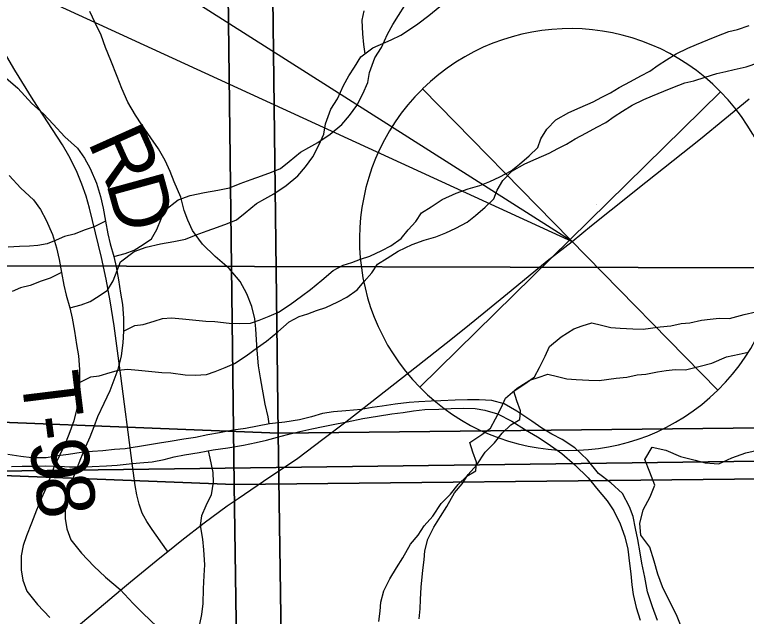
# Model space of a CAD drawing. Extents: x -21.1 to 50.3, y -4.9 to 22.1.
# Drawn here: x 4.587 to 5.308, y 16.789 to 17.38 of the extents above; entities that cross this region are included whole.
import ezdxf

# ---------------------------------------------------------------- set-up
doc = ezdxf.new("R2010")
doc.units = 0
for name, color, linetype in [('GM_X_Major_River', 7, 'Continuous'), ('GM_X_Minor_River', 7, 'Continuous'), ('GM_X_Section', 7, 'Continuous'), ('GM_X_State_Location', 7, 'Continuous'), ('GM_X_State_Route', 7, 'Continuous'), ('GM_X_Township_Road', 7, 'Continuous'), ('GM_X_Township_Road_Text', 7, 'Continuous'), ('SH_Data', 7, 'Continuous')]:
    doc.layers.add(name, color=color, linetype=linetype)

msp = doc.modelspace()

# ---------------------------------------------------------------- linework, layer by layer
at = {"layer": 'GM_X_Major_River'}
for points in [[(4.57886, 17.31807), (4.59071, 17.30792), (4.60449, 17.29285), (4.61595, 17.2827), (4.62552, 17.27253), (4.63701, 17.2601), (4.64924, 17.24881), (4.65615, 17.239), (4.66192, 17.2288), (4.6681, 17.21443), (4.672, 17.20156), (4.67475, 17.18982), (4.67675, 17.17731), (4.67912, 17.16481), (4.68148, 17.15496), (4.68499, 17.14247), (4.68735, 17.13224), (4.68973, 17.11936), (4.69173, 17.10647), (4.69372, 17.09511), (4.69458, 17.08183), (4.69468, 17.06893), (4.69402, 17.05754)], [(4.58223, 17.22201), (4.59372, 17.20958), (4.60595, 17.1983), (4.61286, 17.18849), (4.61863, 17.17829), (4.62481, 17.16392), (4.62871, 17.15105), (4.63146, 17.13931), (4.63346, 17.1268), (4.63584, 17.11429), (4.63819, 17.10445), (4.6417, 17.09195), (4.64406, 17.08173), (4.64644, 17.06884), (4.64844, 17.05596), (4.65043, 17.04459), (4.65129, 17.03131), (4.6514, 17.01841), (4.65073, 17.00702)], [(4.69402, 17.05754), (4.69222, 17.04462), (4.68891, 17.03132), (4.6852, 17.02066), (4.68111, 17.01038), (4.67514, 16.99781), (4.66917, 16.98486), (4.66546, 16.97497), (4.66136, 16.96469), (4.65726, 16.95517), (4.65243, 16.94337), (4.64721, 16.9308), (4.64238, 16.91824), (4.63904, 16.90873), (4.63722, 16.89847), (4.63733, 16.88481), (4.63893, 16.87458), (4.64281, 16.86398), (4.65316, 16.85078), (4.66541, 16.83798), (4.67688, 16.82706), (4.69139, 16.81504), (4.70402, 16.8011), (4.71397, 16.79131), (4.72735, 16.77852)], [(4.65073, 17.00702), (4.64893, 16.99411), (4.64563, 16.9808), (4.64192, 16.97015), (4.63782, 16.95987), (4.63185, 16.9473), (4.62588, 16.93435), (4.62217, 16.92445), (4.61807, 16.91417), (4.61398, 16.90465), (4.60914, 16.89285), (4.60392, 16.88029), (4.59909, 16.86773), (4.59575, 16.85821), (4.59394, 16.84795), (4.59404, 16.83429), (4.59564, 16.82406), (4.59952, 16.81347), (4.60987, 16.80027), (4.62212, 16.78746)]]:
    msp.add_lwpolyline(points, dxfattribs=at)
at = {"layer": 'GM_X_Minor_River'}
for points in [[(4.68499, 17.14247), (4.6961, 17.14529), (4.70522, 17.14876), (4.71394, 17.15413), (4.72229, 17.15987), (4.72756, 17.16902), (4.73169, 17.1793), (4.73507, 17.18767), (4.74834, 17.198), (4.76011, 17.20225), (4.77418, 17.20537), (4.78749, 17.20772), (4.79889, 17.21006), (4.80953, 17.2143), (4.82016, 17.21816), (4.83042, 17.22163), (4.8403, 17.22549), (4.84903, 17.22895), (4.85775, 17.23584), (4.86874, 17.24502), (4.87708, 17.24962), (4.88581, 17.25461), (4.89794, 17.26266), (4.90931, 17.27222), (4.91688, 17.28099), (4.92405, 17.29091), (4.93008, 17.30234), (4.93497, 17.31338), (4.93681, 17.32327), (4.94206, 17.33773), (4.94847, 17.34803), (4.95449, 17.36098), (4.95976, 17.3705), (4.96504, 17.37927), (4.97146, 17.38918)], [(4.6417, 17.09195), (4.65281, 17.09478), (4.66193, 17.09825), (4.67066, 17.10361), (4.679, 17.10936), (4.68427, 17.1185), (4.6884, 17.12878), (4.69178, 17.13716), (4.70505, 17.14749), (4.71682, 17.15173), (4.73089, 17.15485), (4.7442, 17.1572), (4.7556, 17.15954), (4.76624, 17.16378), (4.77688, 17.16764), (4.78713, 17.17112), (4.79701, 17.17497), (4.80574, 17.17844), (4.81446, 17.18532), (4.82545, 17.1945), (4.8338, 17.19911), (4.84252, 17.20409), (4.85466, 17.21214), (4.86602, 17.2217), (4.87359, 17.23048), (4.88076, 17.2404), (4.88679, 17.25182), (4.89168, 17.26287), (4.89352, 17.27275), (4.89877, 17.28722), (4.90518, 17.29751), (4.9112, 17.31046), (4.91648, 17.31999), (4.92176, 17.32875), (4.92817, 17.33867), (4.93992, 17.34747), (4.95815, 17.35555), (4.96764, 17.36016), (4.97598, 17.36552), (4.98432, 17.37127), (4.99494, 17.3793), (5.00593, 17.3881)], [(4.838, 16.97772), (4.83683, 16.98461), (4.83388, 16.99715), (4.8295, 17.02298), (4.82729, 17.03475), (4.82626, 17.05031), (4.82557, 17.06056), (4.82488, 17.07119), (4.82381, 17.08106), (4.82085, 17.09322), (4.816, 17.10577), (4.80925, 17.11795), (4.7987, 17.13054), (4.78474, 17.14239), (4.7723, 17.1546), (4.76252, 17.16794), (4.75803, 17.17822), (4.7543, 17.18772), (4.75097, 17.20064), (4.74462, 17.21586), (4.74051, 17.22613), (4.73565, 17.23678), (4.72889, 17.24821), (4.72137, 17.25926), (4.71273, 17.27183), (4.70634, 17.28135), (4.69883, 17.2943), (4.69285, 17.30762), (4.68837, 17.3194), (4.68203, 17.335), (4.6768, 17.34793), (4.6727, 17.3601), (4.66671, 17.37228), (4.66147, 17.38331)], [(4.93231, 17.34177), (4.93115, 17.35084), (4.92995, 17.36147), (4.92949, 17.37476), (4.93134, 17.38389)], [(4.69468, 17.06893), (4.70564, 17.07469), (4.71401, 17.07549), (4.72464, 17.07897), (4.73301, 17.0813), (4.74176, 17.0821), (4.7528, 17.08102), (4.77565, 17.07887), (4.78441, 17.07854), (4.7985, 17.07672), (4.8084, 17.0764), (4.81944, 17.07684), (4.82817, 17.07992), (4.83805, 17.08378), (4.84716, 17.08763), (4.85854, 17.09529), (4.86991, 17.10333), (4.87863, 17.10984), (4.88962, 17.11901), (4.90098, 17.12857), (4.91085, 17.13395), (4.91921, 17.13665), (4.92795, 17.13974), (4.93706, 17.14283), (4.94883, 17.14821), (4.95756, 17.15282), (4.9678, 17.16009), (4.9746, 17.16849), (4.98217, 17.17689), (4.98783, 17.18528), (4.99731, 17.19141), (5.00831, 17.19831), (5.02198, 17.20484), (5.03376, 17.20909), (5.04516, 17.21219), (5.05503, 17.21604), (5.0649, 17.22066), (5.07591, 17.22679), (5.08424, 17.2333), (5.09372, 17.24133), (5.10242, 17.24973), (5.10542, 17.25811), (5.11108, 17.26763), (5.12016, 17.2768), (5.13268, 17.28409), (5.14407, 17.28909), (5.1566, 17.29448), (5.16533, 17.29909), (5.17368, 17.30331), (5.18241, 17.30868), (5.19341, 17.31444), (5.20366, 17.32019), (5.21239, 17.3248), (5.22073, 17.33054), (5.22907, 17.33591), (5.23856, 17.34166), (5.24994, 17.34742), (5.2583, 17.35088), (5.26969, 17.35551), (5.27843, 17.35897), (5.2902, 17.3636), (5.29894, 17.36554), (5.31034, 17.36941)], [(4.6514, 17.01841), (4.66235, 17.02417), (4.67072, 17.02497), (4.68135, 17.02845), (4.68972, 17.03078), (4.69847, 17.03159), (4.70951, 17.03051), (4.73236, 17.02836), (4.74112, 17.02803), (4.75521, 17.0262), (4.76511, 17.02588), (4.77615, 17.02632), (4.78488, 17.02941), (4.79476, 17.03326), (4.80387, 17.03711), (4.81525, 17.04477), (4.82662, 17.05281), (4.83534, 17.05932), (4.84633, 17.0685), (4.8577, 17.07806), (4.86756, 17.08343), (4.87592, 17.08614), (4.88466, 17.08922), (4.89377, 17.09231), (4.90555, 17.0977), (4.91427, 17.1023), (4.92451, 17.10958), (4.93131, 17.11797), (4.93888, 17.12637), (4.94454, 17.13476), (4.95402, 17.14089), (4.96502, 17.14779), (4.97869, 17.15433), (4.99047, 17.15857), (5.00187, 17.16167), (5.01174, 17.16553), (5.02161, 17.17014), (5.03262, 17.17628), (5.04095, 17.18278), (5.05043, 17.19081), (5.05913, 17.19922), (5.06213, 17.20759), (5.06779, 17.21712), (5.07687, 17.22629), (5.08939, 17.23357), (5.10078, 17.23857), (5.11331, 17.24396), (5.12204, 17.24857), (5.13039, 17.25279), (5.13912, 17.25816), (5.15013, 17.26392), (5.16037, 17.26968), (5.1691, 17.27428), (5.17744, 17.28003), (5.18578, 17.28539), (5.19527, 17.29114), (5.20666, 17.2969), (5.21501, 17.30037), (5.2264, 17.30499), (5.23514, 17.30846), (5.24691, 17.31308), (5.25566, 17.31503), (5.26705, 17.31889), (5.27845, 17.32237), (5.2872, 17.32432), (5.29556, 17.32627), (5.30735, 17.32899), (5.31988, 17.33324)], [(4.67675, 17.17731), (4.66589, 17.17171), (4.65677, 17.16863), (4.64613, 17.16439), (4.63663, 17.16205), (4.62827, 17.15859), (4.61954, 17.15474), (4.61041, 17.15317), (4.60204, 17.15274), (4.59215, 17.15231), (4.58111, 17.15149)], [(4.63346, 17.1268), (4.6226, 17.1212), (4.61348, 17.11811), (4.60284, 17.11387), (4.59334, 17.11154), (4.58499, 17.10807)], [(4.98551, 16.78601), (4.98659, 16.79589), (4.98692, 16.80502), (4.98761, 16.81717), (4.98904, 16.8339), (4.99051, 16.84416), (4.99122, 16.8529), (4.9942, 16.86431), (4.99984, 16.87612), (5.00664, 16.8868), (5.01267, 16.89671), (5.02021, 16.91005), (5.02777, 16.91883), (5.03381, 16.92798), (5.04213, 16.93752), (5.05044, 16.9501), (5.05952, 16.95927), (5.06708, 16.96881), (5.07579, 16.97683), (5.08451, 16.9822), (5.08523, 16.99056), (5.08175, 17.00042), (5.07865, 17.0099), (5.0904, 17.01794), (5.09912, 17.02407), (5.10402, 17.03321), (5.10967, 17.04426), (5.1138, 17.05378), (5.12517, 17.06334), (5.13768, 17.07139), (5.14604, 17.07409), (5.15554, 17.07718), (5.16507, 17.07496), (5.17422, 17.07273), (5.18336, 17.07202), (5.19592, 17.07133), (5.20582, 17.071), (5.22256, 17.07338), (5.23321, 17.0742), (5.24347, 17.07653), (5.25184, 17.07734), (5.26325, 17.07968), (5.272, 17.08087), (5.28075, 17.08168), (5.29102, 17.08135), (5.30547, 17.08523), (5.31687, 17.08795)], [(4.94576, 16.78338), (4.94722, 16.79365), (4.94793, 16.80239), (4.95091, 16.8138), (4.95656, 16.82561), (4.96335, 16.83628), (4.96938, 16.84619), (4.97692, 16.85953), (4.98448, 16.86831), (4.99052, 16.87746), (4.99884, 16.887), (5.00715, 16.89958), (5.01623, 16.90875), (5.02379, 16.91829), (5.0325, 16.92632), (5.04123, 16.93168), (5.04194, 16.94004), (5.03846, 16.9499), (5.03536, 16.95938), (5.04711, 16.96742), (5.05583, 16.97355), (5.06073, 16.98269), (5.06638, 16.99374), (5.07051, 17.00326), (5.08188, 17.01282), (5.09439, 17.02087), (5.10275, 17.02358), (5.11225, 17.02667), (5.12178, 17.02444), (5.13093, 17.02221), (5.14007, 17.0215), (5.15263, 17.02081), (5.16253, 17.02049), (5.17927, 17.02286), (5.18992, 17.02368), (5.20018, 17.02601), (5.20855, 17.02682), (5.21996, 17.02916), (5.22871, 17.03035), (5.23746, 17.03116), (5.24774, 17.03084), (5.26218, 17.03472), (5.27358, 17.03744), (5.28801, 17.0436), (5.30056, 17.04632), (5.3093, 17.04827)], [(5.21997, 16.78457), (5.21512, 16.79788), (5.21028, 16.81271), (5.20772, 16.82714), (5.20477, 16.84082), (5.20294, 16.85108), (5.20075, 16.86399), (5.19855, 16.87501), (5.19597, 16.88678), (5.19261, 16.89629), (5.18549, 16.90923), (5.17417, 16.91993), (5.16209, 16.92911), (5.15117, 16.94245), (5.13872, 16.95429), (5.12625, 16.96233), (5.11604, 16.96771), (5.10621, 16.97346), (5.09639, 16.98035), (5.08165, 16.99031), (5.06918, 16.99759), (5.05705, 17.0007), (5.04453, 17.00154), (5.03315, 17.00161), (5.021, 17.00131), (5.00696, 17.00063), (4.99747, 17.00031), (4.98532, 16.99963), (4.97583, 16.99893), (4.96177, 16.99712), (4.94924, 16.9953), (4.93936, 16.99384), (4.92834, 16.99201), (4.91353, 16.99059), (4.90138, 16.98952), (4.89037, 16.98808), (4.87972, 16.98473), (4.86793, 16.98176), (4.8535, 16.97958), (4.83831, 16.97777), (4.81475, 16.97337), (4.80259, 16.97154), (4.78891, 16.96897), (4.77752, 16.96715), (4.76536, 16.96456), (4.75396, 16.96274), (4.74066, 16.96054), (4.73003, 16.95871), (4.71825, 16.95689), (4.69622, 16.95323), (4.68559, 16.95254), (4.67419, 16.95147), (4.66394, 16.95077), (4.65293, 16.9497), (4.6404, 16.94788), (4.63014, 16.94643), (4.61836, 16.9446), (4.60432, 16.94431), (4.5937, 16.94589), (4.58082, 16.94787)], [(4.58453, 16.93608), (4.59478, 16.9364), (4.60579, 16.93633), (4.61793, 16.93664), (4.63159, 16.93617), (4.64145, 16.93573), (4.6536, 16.93566), (4.66384, 16.93598), (4.67789, 16.93665), (4.68852, 16.93734), (4.70029, 16.93841), (4.71054, 16.93948), (4.7227, 16.94054), (4.73447, 16.94275), (4.74436, 16.94534), (4.75462, 16.94756), (4.76905, 16.94975), (4.78273, 16.95232), (4.79717, 16.95412), (4.81274, 16.95706), (4.82529, 16.95964), (4.83517, 16.96186), (4.84619, 16.96483), (4.85608, 16.96742), (4.86824, 16.97038), (4.88002, 16.97296), (4.89104, 16.97517), (4.90434, 16.97774), (4.9146, 16.97996), (4.93018, 16.98328), (4.94462, 16.98547), (4.95867, 16.98765), (4.96969, 16.9891), (4.97995, 16.99056), (4.99096, 16.99201), (5.005, 16.9923), (5.01715, 16.99298), (5.02892, 16.99329), (5.04068, 16.99284), (5.05016, 16.99126), (5.06266, 16.98777), (5.07665, 16.98047), (5.09026, 16.97204), (5.10198, 16.96514), (5.11256, 16.95825), (5.12578, 16.94868), (5.13861, 16.9376), (5.15181, 16.92462), (5.1601, 16.9147), (5.17064, 16.90212), (5.17703, 16.89221), (5.1834, 16.87965), (5.18786, 16.86672), (5.19082, 16.85456), (5.19263, 16.84051), (5.1937, 16.83026), (5.19477, 16.81964), (5.19622, 16.81014), (5.19917, 16.79722), (5.20289, 16.78468)], [(4.77787, 16.9514), (4.77964, 16.94399), (4.78259, 16.92993), (4.7829, 16.92045), (4.78092, 16.90794), (4.77554, 16.89735), (4.7713, 16.88751), (4.7701, 16.87803), (4.77229, 16.86436), (4.77336, 16.85411), (4.7744, 16.8393), (4.77357, 16.82869), (4.77311, 16.81579), (4.77263, 16.80137), (4.77142, 16.79038), (4.76946, 16.78091)], [(5.24256, 16.78022), (5.23891, 16.79015), (5.23191, 16.80355), (5.22491, 16.81771), (5.22054, 16.82993), (5.21694, 16.8429), (5.2126, 16.85665), (5.20367, 16.86856), (5.2027, 16.87997), (5.20595, 16.89322), (5.21299, 16.90602), (5.21734, 16.91773), (5.2126, 16.93034), (5.20748, 16.94295), (5.21489, 16.955), (5.22813, 16.95214), (5.24285, 16.94584), (5.25723, 16.9422), (5.26706, 16.93939), (5.28034, 16.93843), (5.29334, 16.94431), (5.3071, 16.94942), (5.32005, 16.95226)]]:
    msp.add_lwpolyline(points, dxfattribs=at)
at = {"layer": 'GM_X_Section'}
for points in [[(4.45293, 18.14262), (5.45742, 18.14589), (5.45266, 17.13084), (4.44556, 17.13365)], [(3.80452, 18.01477), (4.83425, 17.98542), (4.84683, 16.96859), (4.43354, 16.98495), (3.82173, 16.99041)], [(4.50247, 17.98887), (5.48815, 17.97251), (5.52017, 16.94387), (4.49435, 16.93023), (4.50289, 17.92975)], [(5.81893, 17.99203), (5.83147, 16.97938), (4.84683, 16.96859), (4.83425, 17.98542)], [(3.76124, 17.96425), (4.79096, 17.9349), (4.80354, 16.91807), (4.39025, 16.93443), (3.77844, 16.93989)], [(5.77564, 17.94152), (5.78818, 16.92886), (4.80354, 16.91807), (4.79096, 17.9349)], [(4.44556, 17.13365), (5.45266, 17.13084), (5.44952, 16.13321), (4.44906, 16.1053)], [(4.84683, 16.96859), (4.86162, 15.95861), (3.83586, 15.97019), (3.82173, 16.99041), (4.43354, 16.98495)], [(4.84683, 16.96859), (5.83147, 16.97938), (5.84702, 15.96751), (4.86162, 15.95861)], [(5.52017, 16.94387), (5.53343, 15.91957), (5.47621, 15.91802), (4.49511, 15.90479), (4.49436, 16.90218), (4.49435, 16.93023)], [(4.80354, 16.91807), (4.81833, 15.90809), (3.79257, 15.91968), (3.77844, 16.93989), (4.39025, 16.93443)], [(4.80354, 16.91807), (5.78818, 16.92886), (5.80373, 15.91699), (4.81833, 15.90809)]]:
    msp.add_lwpolyline(points, close=True, dxfattribs=at)
at = {"layer": 'GM_X_State_Route'}
for points in [[(4.80738, 16.90461), (4.83247, 16.92152), (4.86601, 16.94423), (4.89077, 16.96284), (4.91332, 16.97984), (4.9842, 17.03528), (5.0185, 17.062), (5.03503, 17.07557), (5.04904, 17.08711), (5.07596, 17.10909), (5.11165, 17.13813), (5.13598, 17.15729), (5.15515, 17.17289), (5.17457, 17.18842), (5.20866, 17.21548), (5.26236, 17.25817), (5.3101, 17.29753)], [(4.7382, 16.85243), (4.75199, 16.86343), (4.77411, 16.88068), (4.7965, 16.89728), (4.80738, 16.90461)], [(4.6916, 16.81426), (4.70136, 16.82248), (4.73036, 16.84618), (4.7382, 16.85243)], [(4.64041, 16.77138), (4.64204, 16.77277), (4.67059, 16.79656), (4.6916, 16.81426)]]:
    msp.add_lwpolyline(points, dxfattribs=at)
at = {"layer": 'GM_X_Township_Road'}
for points in [[(4.7382, 16.85243), (4.73707, 16.85401), (4.72285, 16.87389), (4.7177, 16.88171), (4.71454, 16.88712), (4.71312, 16.88995), (4.71189, 16.89286), (4.70993, 16.89886), (4.70776, 16.90798), (4.70615, 16.91711), (4.70343, 16.93643), (4.69919, 16.96962), (4.69568, 16.99735), (4.69192, 17.02507), (4.68542, 17.07438), (4.68151, 17.09891), (4.67751, 17.12027), (4.67284, 17.14149), (4.66115, 17.18982), (4.65772, 17.20172), (4.65372, 17.21344), (4.64912, 17.22493), (4.6452, 17.23333), (4.64082, 17.2415), (4.63444, 17.25211), (4.60579, 17.29652), (4.58782, 17.32563), (4.57514, 17.34705)], [(4.6916, 16.81426), (4.70136, 16.82248), (4.73036, 16.84618), (4.7382, 16.85243)], [(4.64041, 16.77138), (4.64204, 16.77277), (4.67059, 16.79656), (4.6916, 16.81426)]]:
    msp.add_lwpolyline(points, dxfattribs=at)
at = {"layer": 'SH_Data'}
for p, q in [((5.28217, 17.30443), (4.98617, 17.01383)), ((4.98888, 17.30714), (5.27948, 17.01114))]:
    msp.add_line(p, q, dxfattribs=at)
msp.add_lwpolyline([(3.93924, 17.70664), (5.13599, 17.1573), (3.93924, 17.91664)], close=True, dxfattribs=at)
msp.add_arc((5.13417, 17.15913), 0.2074, 134.48425, 134.46773, dxfattribs=at)

# ---------------------------------------------------------------- texts
at = {"layer": 'GM_X_State_Location'}
for s, p in [('s', (5.22652, 17.20699)), ('r', (5.22651, 17.20699))]:
    msp.add_text(s, height=0.000189, dxfattribs=at).set_placement(p)
msp.add_text('241', height=0.000189, rotation=0.00001, dxfattribs=at).set_placement((5.15966, 17.19321))
at = {"layer": 'GM_X_Township_Road_Text'}
for s, rotation, p in [('R', 294.12854, (4.65887, 17.25535)), ('D', 285.33995, (4.67717, 17.21493)), ('T', 277.02031, (4.59345, 17.02589)), ('-', 277.14439, (4.59866, 16.98358)), ('9', 277.58131, (4.60162, 16.95996)), ('8', 279.02779, (4.60647, 16.92372))]:
    msp.add_text(s, height=0.05682, rotation=rotation, dxfattribs=at).set_placement(p)

doc.saveas('drawing.dxf')
